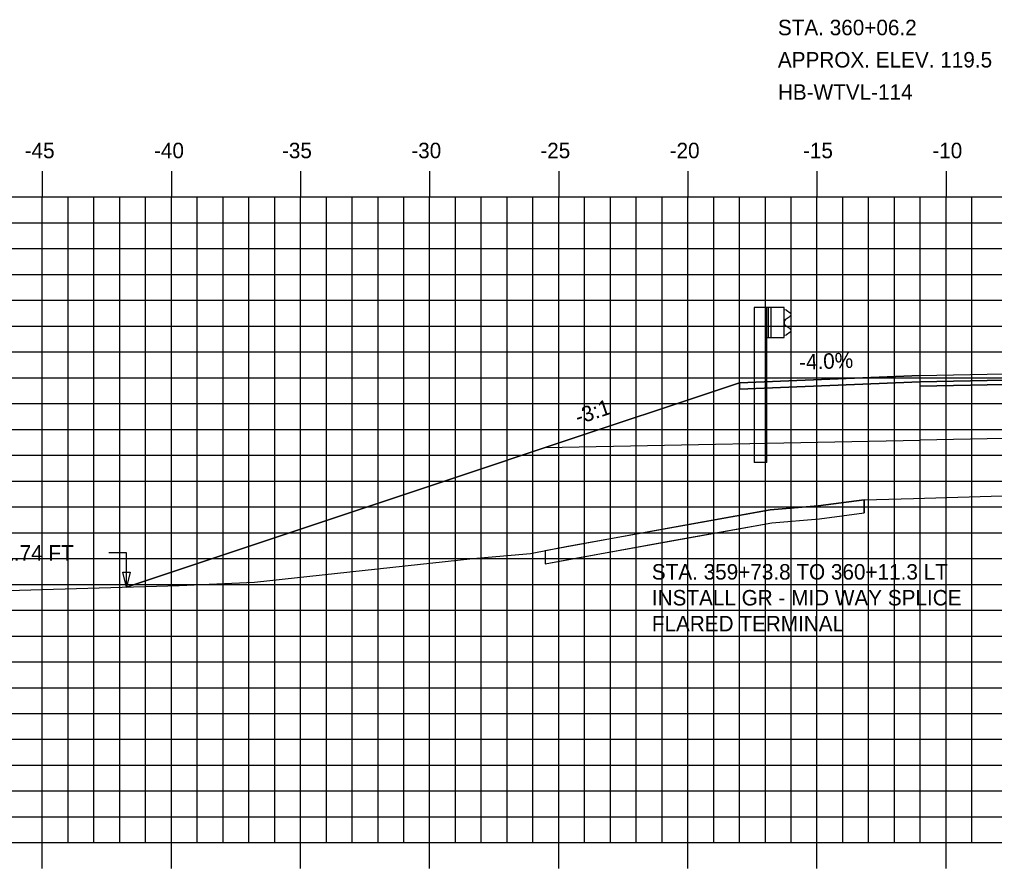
# Model space of a CAD drawing. Extents: x 1146303 to 1146473, y 608981 to 609091.
# Drawn here: x 1146340.03 to 1146377.79, y 609024.33 to 609057.21 of the extents above; entities that cross this region are included whole.
import ezdxf

# ---------------------------------------------------------------- set-up
doc = ezdxf.new("R2010")
doc.units = 0
for name, color, linetype in [('ANNOTATION', 7, 'Continuous'), ('D_Guardrail_Beam_Lt', 7, 'Continuous'), ('D_Roadway_Edge_Shoulder', 7, 'Continuous'), ('D_Roadway_Edge_TW', 7, 'Continuous'), ('D_Roadway_Pavement', 7, 'Continuous'), ('D_Roadway_SlopeLines', 7, 'Continuous'), ('D_Roadway_SubGrade', 7, 'Continuous'), ('D_Text_Standard', 7, 'Continuous'), ('H_V ANNOTATION', 7, 'Continuous'), ('MAJOR', 7, 'Continuous'), ('MINOR', 7, 'Continuous'), ('ROCKS', 7, 'Continuous'), ('S_Roadway_Centerline', 7, 'Continuous'), ('SHADING', 7, 'Continuous')]:
    doc.layers.add(name, color=color, linetype=linetype)

msp = doc.modelspace()

# ---------------------------------------------------------------- linework, layer by layer
msp.add_lwpolyline([(1146344.176, 609035.23), (1146357.382, 609039.632), (1146360.382, 609040.632), (1146367.914, 609043.143), (1146367.915, 609043.143), (1146374.915, 609043.423), (1146385.915, 609043.643), (1146396.915, 609043.423), (1146400.915, 609043.263), (1146408.638, 609040.689), (1146411.638, 609039.689), (1146415.984, 609038.24)])
at = {"layer": 'D_Guardrail_Beam_Lt'}
for p, q in [((1146368.485, 609046.056), (1146368.485, 609040.056)), ((1146368.955, 609046.056), (1146368.485, 609046.056)), ((1146369.643, 609046.056), (1146368.955, 609046.056)), ((1146368.955, 609046.056), (1146368.955, 609044.89)), ((1146369.018, 609046.056), (1146369.018, 609044.89)), ((1146369.122, 609046.056), (1146369.122, 609044.89)), ((1146369.643, 609044.89), (1146369.643, 609046.056)), ((1146369.643, 609045.973), (1146369.717, 609045.959)), ((1146369.733, 609045.952), (1146369.876, 609045.852)), ((1146369.647, 609045.508), (1146369.647, 609045.438)), ((1146369.876, 609045.709), (1146369.681, 609045.573)), ((1146369.681, 609045.374), (1146369.876, 609045.237)), ((1146369.717, 609044.988), (1146369.643, 609044.973)), ((1146369.876, 609045.094), (1146369.733, 609044.994)), ((1146368.955, 609044.89), (1146369.643, 609044.89)), ((1146368.976, 609040.056), (1146368.976, 609044.89)), ((1146368.976, 609040.056), (1146368.485, 609040.056))]:
    msp.add_line(p, q, dxfattribs=at)
for centre, major_axis, start_param, end_param in [((1146369.709, 609045.918), (0.0417, 0), 0.959931, 1.376053), ((1146369.826, 609045.78), (0.0877, 0), 5.323254, 7.243116), ((1146369.726, 609045.508), (-0.0789, 0), 5.323254, 6.283185), ((1146369.726, 609045.438), (-0.0789, 0), 6.283185, 7.243116), ((1146369.709, 609045.028), (0.0417, 0), 4.907132, 5.323254), ((1146369.826, 609045.166), (0.0877, 0), 5.323254, 7.243116)]:
    msp.add_ellipse(centre, major_axis=major_axis, ratio=0.995501, start_param=start_param, end_param=end_param, dxfattribs=at)
at = {"layer": 'D_Roadway_Edge_Shoulder'}
msp.add_lwpolyline([(1146374.915, 609043.423), (1146367.915, 609043.143), (1146367.915, 609042.893), (1146374.915, 609043.173)], close=True, dxfattribs=at)
at = {"layer": 'D_Roadway_Edge_TW'}
msp.add_lwpolyline([(1146374.915, 609043.173), (1146374.915, 609043.423), (1146385.915, 609043.643), (1146396.915, 609043.423), (1146396.915, 609043.173), (1146385.915, 609043.393)], close=True, dxfattribs=at)
at = {"layer": 'D_Roadway_Pavement'}
msp.add_lwpolyline([(1146374.915, 609043.006), (1146374.915, 609043.173), (1146385.915, 609043.393), (1146396.915, 609043.173), (1146396.915, 609043.007), (1146385.915, 609043.227)], close=True, dxfattribs=at)
at = {"layer": 'D_Roadway_SlopeLines'}
for points in [[(1146360.382, 609040.632), (1146357.382, 609039.632)], [(1146357.382, 609039.632), (1146344.176, 609035.23)]]:
    msp.add_lwpolyline(points, dxfattribs=at)
at = {"layer": 'D_Roadway_SubGrade'}
for p, q in [((1146372.738, 609038.608), (1146372.738, 609038.108)), ((1146360.382, 609036.636), (1146360.382, 609036.128))]:
    msp.add_line(p, q, dxfattribs=at)
for points in [[(1146374.915, 609043.006), (1146374.915, 609043.173), (1146367.915, 609042.893), (1146367.915, 609043.143), (1146367.914, 609043.143), (1146360.382, 609040.632), (1146374.915, 609040.923)], [(1146374.915, 609040.923), (1146374.915, 609043.006), (1146385.915, 609043.227), (1146396.915, 609043.007), (1146396.915, 609040.923), (1146385.915, 609041.143)]]:
    msp.add_lwpolyline(points, close=True, dxfattribs=at)
msp.add_lwpolyline([(1146360.382, 609036.128), (1146361.359, 609036.317), (1146369.163, 609037.72), (1146371.015, 609037.874), (1146372.738, 609038.105)], dxfattribs=at)
at = {"layer": 'D_Text_Standard'}
msp.add_lwpolyline([(1146344.176, 609035.23), (1146344.169, 609036.553), (1146343.489, 609036.553)], dxfattribs=at)
msp.add_lwpolyline([(1146344.176, 609035.23), (1146344.027, 609035.812), (1146344.318, 609035.813)], close=True, dxfattribs=at)
at = {"layer": 'MAJOR'}
for p, q in [((1146340.915, 609051.337), (1146340.915, 609050.335)), ((1146345.915, 609051.337), (1146345.915, 609050.335)), ((1146350.915, 609051.337), (1146350.915, 609050.335)), ((1146355.915, 609051.337), (1146355.915, 609050.335)), ((1146360.915, 609051.337), (1146360.915, 609050.335)), ((1146365.915, 609051.337), (1146365.915, 609050.335)), ((1146370.915, 609051.337), (1146370.915, 609050.335)), ((1146375.915, 609051.337), (1146375.915, 609050.335)), ((1146315.915, 609050.335), (1146455.915, 609050.335)), ((1146315.915, 609050.335), (1146455.915, 609050.335)), ((1146340.915, 609025.335), (1146340.915, 609050.335)), ((1146345.915, 609025.335), (1146345.915, 609050.335)), ((1146350.915, 609025.335), (1146350.915, 609050.335)), ((1146355.915, 609025.335), (1146355.915, 609050.335)), ((1146360.915, 609025.335), (1146360.915, 609050.335)), ((1146365.915, 609025.335), (1146365.915, 609050.335)), ((1146370.915, 609025.335), (1146370.915, 609050.335)), ((1146375.915, 609025.335), (1146375.915, 609050.335)), ((1146315.915, 609045.335), (1146455.915, 609045.335)), ((1146315.915, 609040.335), (1146455.915, 609040.335)), ((1146315.915, 609035.335), (1146455.915, 609035.335)), ((1146315.915, 609030.335), (1146455.915, 609030.335)), ((1146315.915, 609025.335), (1146455.915, 609025.335)), ((1146315.915, 609025.335), (1146455.915, 609025.335)), ((1146340.915, 609024.333), (1146340.915, 609025.335)), ((1146345.915, 609024.333), (1146345.915, 609025.335)), ((1146350.915, 609024.333), (1146350.915, 609025.335)), ((1146355.915, 609024.333), (1146355.915, 609025.335)), ((1146360.915, 609024.333), (1146360.915, 609025.335)), ((1146365.915, 609024.333), (1146365.915, 609025.335)), ((1146370.915, 609024.333), (1146370.915, 609025.335)), ((1146375.915, 609024.333), (1146375.915, 609025.335))]:
    msp.add_line(p, q, dxfattribs=at)
at = {"layer": 'MINOR'}
for p, q in [((1146341.915, 609025.335), (1146341.915, 609050.335)), ((1146342.915, 609025.335), (1146342.915, 609050.335)), ((1146343.915, 609025.335), (1146343.915, 609050.335)), ((1146344.915, 609025.335), (1146344.915, 609050.335)), ((1146346.915, 609025.335), (1146346.915, 609050.335)), ((1146347.915, 609025.335), (1146347.915, 609050.335)), ((1146348.915, 609025.335), (1146348.915, 609050.335)), ((1146349.915, 609025.335), (1146349.915, 609050.335)), ((1146351.915, 609025.335), (1146351.915, 609050.335)), ((1146352.915, 609025.335), (1146352.915, 609050.335)), ((1146353.915, 609025.335), (1146353.915, 609050.335)), ((1146354.915, 609025.335), (1146354.915, 609050.335)), ((1146356.915, 609025.335), (1146356.915, 609050.335)), ((1146357.915, 609025.335), (1146357.915, 609050.335)), ((1146358.915, 609025.335), (1146358.915, 609050.335)), ((1146359.915, 609025.335), (1146359.915, 609050.335)), ((1146361.915, 609025.335), (1146361.915, 609050.335)), ((1146362.915, 609025.335), (1146362.915, 609050.335)), ((1146363.915, 609025.335), (1146363.915, 609050.335)), ((1146364.915, 609025.335), (1146364.915, 609050.335)), ((1146366.915, 609025.335), (1146366.915, 609050.335)), ((1146367.915, 609025.335), (1146367.915, 609050.335)), ((1146368.915, 609025.335), (1146368.915, 609050.335)), ((1146369.915, 609025.335), (1146369.915, 609050.335)), ((1146371.915, 609025.335), (1146371.915, 609050.335)), ((1146372.915, 609025.335), (1146372.915, 609050.335)), ((1146373.915, 609025.335), (1146373.915, 609050.335)), ((1146374.915, 609025.335), (1146374.915, 609050.335)), ((1146376.915, 609025.335), (1146376.915, 609050.335)), ((1146315.915, 609049.335), (1146455.915, 609049.335)), ((1146315.915, 609048.335), (1146455.915, 609048.335)), ((1146315.915, 609047.335), (1146455.915, 609047.335)), ((1146315.915, 609046.335), (1146455.915, 609046.335)), ((1146315.915, 609044.335), (1146455.915, 609044.335)), ((1146315.915, 609043.335), (1146455.915, 609043.335)), ((1146315.915, 609042.335), (1146455.915, 609042.335)), ((1146315.915, 609041.335), (1146455.915, 609041.335)), ((1146315.915, 609039.335), (1146455.915, 609039.335)), ((1146315.915, 609038.335), (1146455.915, 609038.335)), ((1146315.915, 609037.335), (1146455.915, 609037.335)), ((1146315.915, 609036.335), (1146455.915, 609036.335)), ((1146315.915, 609034.335), (1146455.915, 609034.335)), ((1146315.915, 609033.335), (1146455.915, 609033.335)), ((1146315.915, 609032.335), (1146455.915, 609032.335)), ((1146315.915, 609031.335), (1146455.915, 609031.335)), ((1146315.915, 609029.335), (1146455.915, 609029.335)), ((1146315.915, 609028.335), (1146455.915, 609028.335)), ((1146315.915, 609027.335), (1146455.915, 609027.335)), ((1146315.915, 609026.335), (1146455.915, 609026.335))]:
    msp.add_line(p, q, dxfattribs=at)
at = {"layer": 'S_Roadway_Centerline'}
msp.add_lwpolyline([(1146333.388, 609034.911), (1146346.209, 609035.291), (1146349.129, 609035.414), (1146357.59, 609036.333), (1146359.818, 609036.527), (1146361.268, 609036.808), (1146369.098, 609038.216), (1146370.961, 609038.37), (1146372.738, 609038.608), (1146374.647, 609038.666), (1146383.693, 609038.936), (1146385.688, 609038.859), (1146395.034, 609038.539), (1146397.895, 609038.178), (1146398.57, 609038.098), (1146401.631, 609036.957), (1146404.946, 609035.238), (1146408.835, 609036.389), (1146410.172, 609037.511), (1146433.848, 609040.479), (1146437.527, 609040.851)], dxfattribs=at)
at = {"layer": 'SHADING'}
msp.add_lwpolyline([(1146360.382, 609036.636), (1146360.382, 609036.128), (1146365.261, 609037.019), (1146369.163, 609037.72), (1146371.015, 609037.874), (1146372.738, 609038.105), (1146372.738, 609038.608), (1146371.85, 609038.489), (1146370.961, 609038.37), (1146369.098, 609038.216), (1146365.183, 609037.512)], close=True, dxfattribs=at)

# ---------------------------------------------------------------- texts
at = {"layer": 'ANNOTATION'}
for s, rotation, p in [('-4.0%', 2.2906, (1146370.231, 609043.637)), ('-3:1', 18.4348, (1146361.665, 609041.514))]:
    msp.add_text(s, height=0.6, rotation=rotation, dxfattribs=at).set_placement(p)
for s, p in [('STA. 359+73.8 TO 360+11.3 LT', (1146364.519, 609035.52)), ('INSTALL GR - MID WAY SPLICE', (1146364.519, 609034.518)), ('FLARED TERMINAL', (1146364.519, 609033.516))]:
    msp.add_text(s, height=0.6, dxfattribs=at).set_placement(p)
at = {"layer": 'D_Text_Standard'}
msp.add_text('-41.74 FT', height=0.6, dxfattribs=at).set_placement((1146338.655, 609036.253))
at = {"layer": 'H_V ANNOTATION'}
for s, p in [('-45', (1146340.232, 609051.835)), ('-40', (1146345.24, 609051.835)), ('-35', (1146350.195, 609051.835)), ('-30', (1146355.203, 609051.835)), ('-25', (1146360.2, 609051.835)), ('-20', (1146365.208, 609051.835)), ('-15', (1146370.372, 609051.835)), ('-10', (1146375.38, 609051.835))]:
    msp.add_text(s, height=0.6, dxfattribs=at).set_placement(p)
at = {"layer": 'ROCKS'}
for s, p in [('STA. 360+06.2', (1146369.401, 609056.598)), ('APPROX. ELEV. 119.5', (1146369.401, 609055.348)), ('HB-WTVL-114', (1146369.401, 609054.098))]:
    msp.add_text(s, height=0.6, rotation=360, dxfattribs=at).set_placement(p)

doc.saveas('drawing.dxf')
